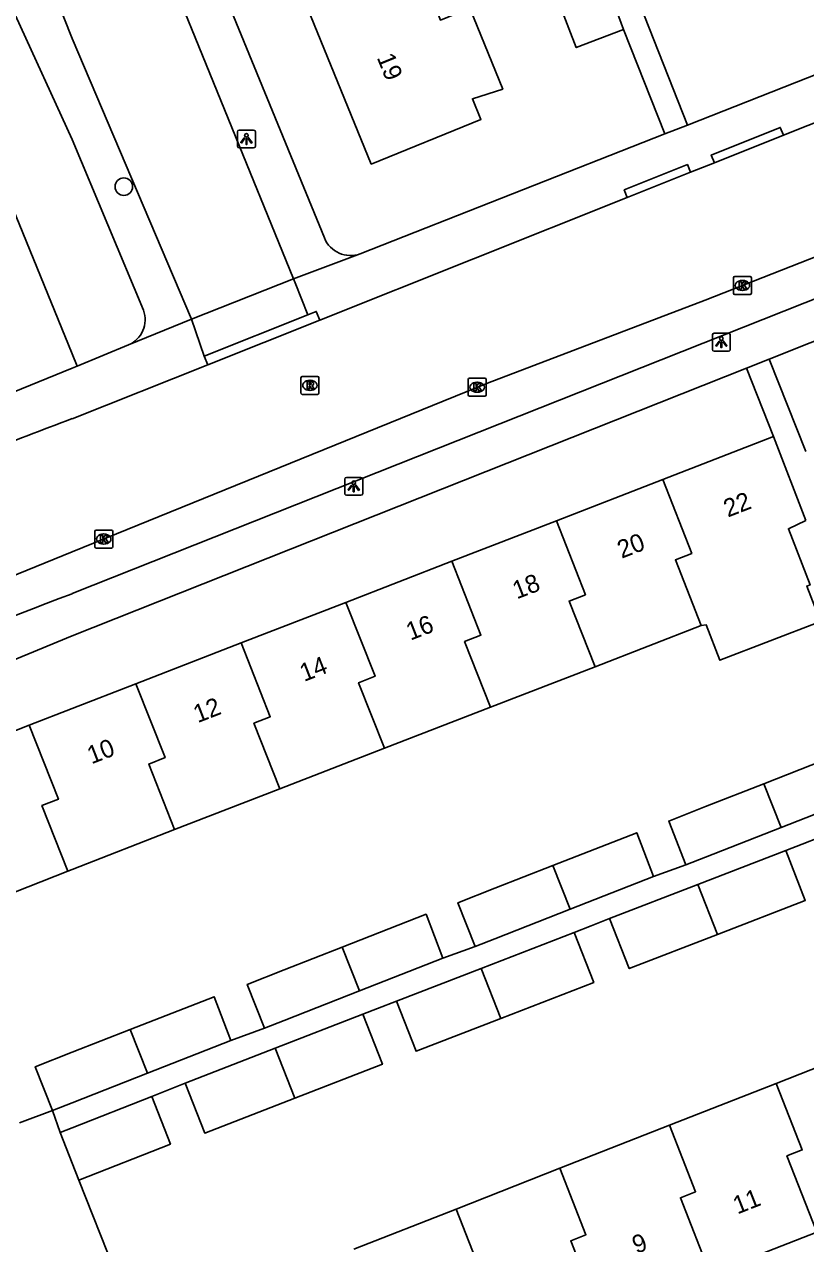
# Model space of a CAD drawing. Extents: x 162990 to 165007, y 383433 to 384336.
# Drawn here: x 163997.3 to 164040.8, y 383839.9 to 383907.8 of the extents above; entities that cross this region are included whole.
import ezdxf

# ---------------------------------------------------------------- set-up
doc = ezdxf.new("R2010")
doc.units = 0
for name, color, linetype in [('IMGEO_Boom', 7, 'Continuous'), ('IMGEO_Kolk', 7, 'Continuous'), ('IMGEO_Lichtpunt', 7, 'Continuous'), ('IMGEO_Pand', 7, 'Continuous'), ('IMGEO_Pand_nummerreeks', 7, 'Continuous'), ('IMGEO_Rijbaan_lokaal_open', 7, 'Continuous'), ('IMGEO_Rioolput', 7, 'Continuous'), ('IMGEO_Voetpad_open', 7, 'Continuous')]:
    doc.layers.add(name, color=color, linetype=linetype)

msp = doc.modelspace()

# ---------------------------------------------------------------- linework, layer by layer
at = {"layer": 'IMGEO_Boom'}
msp.add_circle((164002.875, 383898.73), 0.489, dxfattribs=at)
at = {"layer": 'IMGEO_Kolk'}
for p, q in [((164036.774, 383892.807), (164036.774, 383893.659)), ((164036.849, 383893.733), (164037.701, 383893.733)), ((164037.262, 383893.513), (164037.287, 383893.513)), ((164037.775, 383893.659), (164037.775, 383892.807)), ((164037.701, 383892.733), (164036.849, 383892.733)), ((164037.285, 383892.953), (164037.26, 383892.953)), ((164022.023, 383887.143), (164022.023, 383887.995)), ((164022.098, 383888.069), (164022.95, 383888.069)), ((164022.511, 383887.849), (164022.536, 383887.849)), ((164023.024, 383887.995), (164023.024, 383887.143)), ((164022.95, 383887.069), (164022.098, 383887.069)), ((164022.534, 383887.289), (164022.509, 383887.289)), ((164001.258, 383878.697), (164001.258, 383879.549)), ((164001.333, 383879.623), (164002.185, 383879.623)), ((164002.259, 383879.549), (164002.259, 383878.697)), ((164001.746, 383879.403), (164001.771, 383879.403)), ((164002.185, 383878.623), (164001.333, 383878.623)), ((164001.769, 383878.843), (164001.744, 383878.843))]:
    msp.add_line(p, q, dxfattribs=at)
for points in [[(164036.774, 383892.807), (164036.774, 383893.659)], [(164036.849, 383893.733), (164037.701, 383893.733)], [(164037.095, 383893.433), (164037.218, 383893.433), (164037.218, 383893.282), (164037.348, 383893.433), (164037.512, 383893.433), (164037.366, 383893.282), (164037.519, 383893.033), (164037.367, 383893.033), (164037.282, 383893.197), (164037.218, 383893.13), (164037.218, 383893.033), (164037.095, 383893.033), (164037.095, 383893.433)], [(164037.775, 383893.659), (164037.775, 383892.807)], [(164037.701, 383892.733), (164036.849, 383892.733)], [(164022.023, 383887.143), (164022.023, 383887.995)], [(164022.098, 383888.069), (164022.95, 383888.069)], [(164022.344, 383887.769), (164022.467, 383887.769), (164022.467, 383887.618), (164022.597, 383887.769), (164022.761, 383887.769), (164022.615, 383887.618), (164022.768, 383887.369), (164022.616, 383887.369), (164022.531, 383887.533), (164022.467, 383887.466), (164022.467, 383887.369), (164022.344, 383887.369), (164022.344, 383887.769)], [(164023.024, 383887.995), (164023.024, 383887.143)], [(164022.95, 383887.069), (164022.098, 383887.069)], [(164001.258, 383878.697), (164001.258, 383879.549)], [(164001.333, 383879.623), (164002.185, 383879.623)], [(164002.259, 383879.549), (164002.259, 383878.697)], [(164001.579, 383879.323), (164001.702, 383879.323), (164001.702, 383879.172), (164001.832, 383879.323), (164001.996, 383879.323), (164001.85, 383879.172), (164002.003, 383878.923), (164001.851, 383878.923), (164001.766, 383879.087), (164001.702, 383879.02), (164001.702, 383878.923), (164001.579, 383878.923), (164001.579, 383879.323)], [(164002.185, 383878.623), (164001.333, 383878.623)]]:
    msp.add_lwpolyline(points, dxfattribs=at)
for centre, start, end in [((164036.851, 383893.657), 91.55205, 178.44795), ((164036.851, 383893.657), 91.55205, 178.44795), ((164037.699, 383893.657), 1.55205, 88.44795), ((164037.699, 383893.657), 1.55205, 88.44795), ((164036.851, 383892.809), 181.55205, 268.44795), ((164036.851, 383892.809), 181.55205, 268.44795), ((164037.699, 383892.809), 271.55205, 358.44795), ((164037.699, 383892.809), 271.55205, 358.44795), ((164022.1, 383887.993), 91.55205, 178.44795), ((164022.1, 383887.993), 91.55205, 178.44795), ((164022.948, 383887.993), 1.55205, 88.44795), ((164022.948, 383887.993), 1.55205, 88.44795), ((164022.1, 383887.145), 181.55205, 268.44795), ((164022.1, 383887.145), 181.55205, 268.44795), ((164022.948, 383887.145), 271.55205, 358.44795), ((164022.948, 383887.145), 271.55205, 358.44795), ((164001.335, 383879.547), 91.55205, 178.44795), ((164001.335, 383879.547), 91.55205, 178.44795), ((164002.183, 383879.547), 1.55205, 88.44795), ((164002.183, 383879.547), 1.55205, 88.44795), ((164001.335, 383878.699), 181.55205, 268.44795), ((164001.335, 383878.699), 181.55205, 268.44795), ((164002.183, 383878.699), 271.55205, 358.44795), ((164002.183, 383878.699), 271.55205, 358.44795)]:
    msp.add_arc(centre, 0.0765, start, end, dxfattribs=at)
for centre, major_axis, ratio, start_param, end_param in [((164037.261, 383893.233), (-0.387, 0.002), 0.722429, 4.712389, 7.853982), ((164037.286, 383893.233), (-0.39, 0.002), 0.717154, 1.570796, 4.712389), ((164022.51, 383887.569), (-0.387, 0.002), 0.722429, 4.712389, 7.853982), ((164022.535, 383887.569), (-0.39, 0.002), 0.717154, 1.570796, 4.712389), ((164001.745, 383879.123), (-0.387, 0.002), 0.722429, 4.712389, 7.853982), ((164001.77, 383879.123), (-0.39, 0.002), 0.717154, 1.570796, 4.712389)]:
    msp.add_ellipse(centre, major_axis=major_axis, ratio=ratio, start_param=start_param, end_param=end_param, dxfattribs=at)
at = {"layer": 'IMGEO_Lichtpunt'}
for p, q in [((164009.193, 383901.785), (164009.193, 383900.978)), ((164009.193, 383901.785), (164009.193, 383900.978)), ((164010.095, 383901.88), (164009.287, 383901.88)), ((164010.095, 383901.88), (164009.287, 383901.88)), ((164010.189, 383900.978), (164010.189, 383901.785)), ((164010.189, 383900.978), (164010.189, 383901.785)), ((164009.287, 383900.884), (164010.095, 383900.884)), ((164009.287, 383900.884), (164010.095, 383900.884)), ((164035.608, 383890.478), (164035.608, 383889.671)), ((164035.608, 383890.478), (164035.608, 383889.671)), ((164036.51, 383890.573), (164035.702, 383890.573)), ((164036.51, 383890.573), (164035.702, 383890.573)), ((164036.604, 383889.671), (164036.604, 383890.478)), ((164036.604, 383889.671), (164036.604, 383890.478)), ((164035.702, 383889.577), (164036.51, 383889.577)), ((164035.702, 383889.577), (164036.51, 383889.577)), ((164015.162, 383882.459), (164015.162, 383881.652)), ((164015.162, 383882.459), (164015.162, 383881.652)), ((164016.064, 383882.554), (164015.256, 383882.554)), ((164016.064, 383882.554), (164015.256, 383882.554)), ((164016.158, 383881.652), (164016.158, 383882.459)), ((164016.158, 383881.652), (164016.158, 383882.459)), ((164015.256, 383881.558), (164016.064, 383881.558)), ((164015.256, 383881.558), (164016.064, 383881.558))]:
    msp.add_line(p, q, dxfattribs=at)
for points in [[(164009.567, 383901.449), (164009.606, 383901.421), (164009.418, 383901.159), (164009.38, 383901.186), (164009.567, 383901.449)], [(164009.669, 383901.401), (164009.716, 383901.401), (164009.716, 383901.079), (164009.669, 383901.079), (164009.669, 383901.401)], [(164009.779, 383901.421), (164009.817, 383901.448), (164010.004, 383901.186), (164009.965, 383901.158), (164009.779, 383901.421)], [(164035.982, 383890.142), (164036.021, 383890.114), (164035.833, 383889.852), (164035.795, 383889.879), (164035.982, 383890.142)], [(164036.084, 383890.094), (164036.131, 383890.094), (164036.131, 383889.772), (164036.084, 383889.772), (164036.084, 383890.094)], [(164036.194, 383890.114), (164036.232, 383890.141), (164036.419, 383889.879), (164036.38, 383889.851), (164036.194, 383890.114)], [(164015.536, 383882.123), (164015.575, 383882.095), (164015.387, 383881.833), (164015.349, 383881.86), (164015.536, 383882.123)], [(164015.638, 383882.075), (164015.685, 383882.075), (164015.685, 383881.753), (164015.638, 383881.753), (164015.638, 383882.075)], [(164015.748, 383882.095), (164015.786, 383882.122), (164015.973, 383881.86), (164015.934, 383881.832), (164015.748, 383882.095)]]:
    msp.add_lwpolyline(points, dxfattribs=at)
for centre in [(164009.692, 383901.583), (164036.107, 383890.276), (164015.661, 383882.257)]:
    msp.add_circle(centre, 0.0994, dxfattribs=at)
for centre, start, end in [((164009.287, 383901.785), 90, 180), ((164009.287, 383901.785), 90, 180), ((164010.095, 383901.785), 0, 90), ((164010.095, 383901.785), 0, 90), ((164009.287, 383900.978), 180, 270), ((164009.287, 383900.978), 180, 270), ((164010.095, 383900.978), 270, 0), ((164010.095, 383900.978), 270, 360), ((164035.702, 383890.478), 90, 180), ((164035.702, 383890.478), 90, 180), ((164036.51, 383890.478), 0, 90), ((164036.51, 383890.478), 0, 90), ((164035.702, 383889.671), 180, 270), ((164035.702, 383889.671), 180, 270), ((164036.51, 383889.671), 270, 0), ((164036.51, 383889.671), 270, 360), ((164015.256, 383882.459), 90, 180), ((164015.256, 383882.459), 90, 180), ((164016.064, 383882.459), 0, 90), ((164016.064, 383882.459), 0, 90), ((164015.256, 383881.652), 180, 270), ((164015.256, 383881.652), 180, 270), ((164016.064, 383881.652), 270, 0), ((164016.064, 383881.652), 270, 360)]:
    msp.add_arc(centre, 0.0946, start, end, dxfattribs=at)
at = {"layer": 'IMGEO_Pand'}
for points in [[(164028.022, 383914.647), (164030.669, 383907.485)], [(164025.298, 383913.569), (164028.032, 383906.469), (164030.669, 383907.485)], [(164013.083, 383908.672), (164016.634, 383899.987), (164022.732, 383902.472), (164022.262, 383903.627), (164023.948, 383904.165), (164022.121, 383908.669), (164020.483, 383908.004), (164019.203, 383911.158)], [(163996.678, 383897.58), (164000, 383889.428), (164000.279, 383888.743)], [(164000.279, 383888.743), (164000, 383888.629), (163994.349, 383886.325)], [(164032.842, 383882.428), (164039.01, 383884.819)], [(164039.01, 383884.819), (164040.81, 383880.155)], [(164026.929, 383880.136), (164032.842, 383882.428)], [(164034.992, 383874.308), (164033.552, 383877.958), (164034.462, 383878.318), (164032.842, 383882.428)], [(164021.115, 383877.882), (164026.929, 383880.136)], [(164026.929, 383880.136), (164028.549, 383876.026), (164027.639, 383875.666), (164029.079, 383872.016)], [(164040.81, 383880.155), (164039.832, 383879.698), (164041.038, 383876.572), (164040.851, 383876.5), (164041.611, 383874.532), (164036.023, 383872.374), (164035.263, 383874.343), (164034.992, 383874.308)], [(164015.224, 383875.598), (164021.115, 383877.882)], [(164021.115, 383877.882), (164022.735, 383873.772), (164021.825, 383873.412), (164023.265, 383869.762)], [(164009.4, 383873.339), (164015.224, 383875.598)], [(164017.374, 383867.478), (164015.934, 383871.128), (164016.844, 383871.488), (164015.224, 383875.598)], [(164034.992, 383874.308), (164029.079, 383872.016)], [(164003.547, 383871.07), (164009.4, 383873.339)], [(164011.55, 383865.219), (164010.11, 383868.869), (164011.02, 383869.229), (164009.4, 383873.339)], [(164029.079, 383872.016), (164023.265, 383869.762)], [(163997.613, 383868.756), (164000, 383869.697), (164003.547, 383871.07)], [(164003.547, 383871.07), (164005.167, 383866.96), (164004.257, 383866.6), (164005.697, 383862.95)], [(164023.265, 383869.762), (164017.374, 383867.478)], [(163991.679, 383866.418), (163997.613, 383868.756)], [(163999.762, 383860.636), (163998.323, 383864.285), (163999.233, 383864.645), (163997.613, 383868.756)], [(164017.374, 383867.478), (164011.55, 383865.219)], [(164038.467, 383865.501), (164043.125, 383867.327)], [(164043.125, 383867.327), (164044.064, 383864.882), (164039.427, 383863.066)], [(164034.136, 383860.993), (164033.177, 383863.427), (164035.23, 383864.232), (164038.467, 383865.501)], [(164038.467, 383865.501), (164039.427, 383863.066)], [(164011.55, 383865.219), (164005.697, 383862.95)], [(164005.697, 383862.95), (164000, 383860.73), (163999.762, 383860.636)], [(164026.74, 383860.955), (164031.398, 383862.781), (164032.337, 383860.336)], [(164039.427, 383863.066), (164035.23, 383861.422), (164034.136, 383860.993)], [(164039.683, 383861.792), (164034.803, 383859.901)], [(164035.895, 383857.119), (164040.775, 383859.011), (164039.683, 383861.792)], [(163999.762, 383860.636), (163993.829, 383858.298)], [(164022.409, 383856.447), (164021.45, 383858.881), (164023.503, 383859.686), (164026.74, 383860.955)], [(164027.7, 383858.52), (164026.74, 383860.955)], [(164032.337, 383860.336), (164027.7, 383858.52)], [(164034.803, 383859.901), (164029.893, 383857.998)], [(164035.895, 383857.119), (164034.803, 383859.901)], [(164027.7, 383858.52), (164023.503, 383856.876), (164022.409, 383856.447)], [(164015.025, 383856.412), (164019.683, 383858.238), (164020.622, 383855.793)], [(164029.893, 383857.998), (164030.985, 383855.216), (164035.895, 383857.119)], [(164027.916, 383857.231), (164022.756, 383855.231)], [(164023.847, 383852.45), (164029.008, 383854.45), (164027.916, 383857.231)], [(164010.694, 383851.904), (164009.735, 383854.338), (164011.788, 383855.143), (164015.025, 383856.412)], [(164015.985, 383853.977), (164015.025, 383856.412)], [(164020.622, 383855.793), (164015.985, 383853.977)], [(164022.756, 383855.231), (164018.032, 383853.401)], [(164023.847, 383852.45), (164022.756, 383855.231)], [(164015.985, 383853.977), (164011.788, 383852.333), (164010.694, 383851.904)], [(164003.235, 383851.828), (164007.895, 383853.655), (164008.834, 383851.21)], [(164018.032, 383853.401), (164019.124, 383850.619), (164023.847, 383852.45)], [(164011.29, 383850.787), (164016.167, 383852.678)], [(164012.382, 383848.006), (164017.26, 383849.896), (164016.167, 383852.678)], [(163998.906, 383847.321), (163997.947, 383849.755), (164000, 383850.56), (164003.235, 383851.828)], [(164004.196, 383849.393), (164003.235, 383851.828)], [(164008.834, 383851.21), (164004.196, 383849.393)], [(164039.151, 383848.825), (164044.939, 383851.097)], [(164006.284, 383848.847), (164011.29, 383850.787)], [(164011.29, 383850.787), (164012.382, 383848.006)], [(164004.196, 383849.393), (164000, 383847.75), (163998.906, 383847.321)], [(164012.382, 383848.006), (164007.376, 383846.066), (164006.284, 383848.847)], [(164033.22, 383846.498), (164039.151, 383848.825)], [(164041.417, 383840.56), (164039.756, 383844.796), (164040.601, 383845.131), (164039.151, 383848.825)], [(163999.326, 383846.101), (164000, 383846.365), (164004.427, 383848.103)], [(164000.366, 383843.452), (164005.467, 383845.455), (164004.427, 383848.103)], [(164027.123, 383844.105), (164033.22, 383846.498)], [(164035.485, 383838.232), (164033.825, 383842.468), (164034.67, 383842.803), (164033.22, 383846.498)], [(163999.326, 383846.101), (164000, 383844.384), (164000.366, 383843.452)], [(164021.352, 383841.84), (164027.123, 383844.105)], [(164027.123, 383844.105), (164028.573, 383840.411), (164027.728, 383840.076), (164029.389, 383835.84)], [(164015.675, 383839.613), (164021.352, 383841.84)], [(164021.352, 383841.84), (164022.802, 383838.146), (164021.957, 383837.811), (164023.617, 383833.575)], [(164041.417, 383840.56), (164035.485, 383838.232)]]:
    msp.add_lwpolyline(points, dxfattribs=at)
at = {"layer": 'IMGEO_Rijbaan_lokaal_open'}
for points in [[(164012.318, 383893.596), (164004.63, 383912.46), (164000, 383924.312), (163980.791, 383970.272)], [(163988.382, 383936.273), (164000, 383906.981), (164006.644, 383891.352)], [(164052.116, 383906.595), (164039.558, 383901.589)], [(164039.558, 383901.589), (164035.716, 383900.057)], [(164035.716, 383900.057), (164034.39, 383899.529)], [(163987.058, 383873.134), (164000, 383878.405), (164023.091, 383887.799), (164035.209, 383892.416), (164053.748, 383899.705)], [(164034.39, 383899.529), (164030.872, 383898.127)], [(164030.872, 383898.127), (164013.768, 383891.308)], [(164006.644, 383891.352), (164012.318, 383893.596)], [(164013.768, 383891.308), (164007.539, 383888.825)], [(164007.539, 383888.825), (164000, 383885.82)]]:
    msp.add_lwpolyline(points, dxfattribs=at)
msp.add_arc((164167.038, 383443.254), 473.04, 110.67806, 111.97431, dxfattribs=at)
at = {"layer": 'IMGEO_Rioolput'}
for p, q in [((164012.725, 383887.248), (164012.725, 383888.1)), ((164012.8, 383888.174), (164013.652, 383888.174)), ((164013.213, 383887.954), (164013.238, 383887.954)), ((164013.726, 383888.1), (164013.726, 383887.248)), ((164013.652, 383887.174), (164012.8, 383887.174)), ((164013.236, 383887.394), (164013.211, 383887.394))]:
    msp.add_line(p, q, dxfattribs=at)
for points in [[(164012.725, 383887.248), (164012.725, 383888.1)], [(164012.8, 383888.174), (164013.652, 383888.174)], [(164013.314, 383887.872), (164013.062, 383887.874), (164013.062, 383887.474)], [(164013.24, 383887.793), (164013.186, 383887.793), (164013.186, 383887.712)], [(164013.186, 383887.712), (164013.238, 383887.712)], [(164013.726, 383888.1), (164013.726, 383887.248)], [(164013.652, 383887.174), (164012.8, 383887.174)], [(164013.062, 383887.474), (164013.186, 383887.474), (164013.186, 383887.636), (164013.197, 383887.636)], [(164013.244, 383887.607), (164013.315, 383887.474), (164013.455, 383887.474), (164013.39, 383887.6)]]:
    msp.add_lwpolyline(points, dxfattribs=at)
for centre, radius, start, end in [((164012.802, 383888.098), 0.0765, 91.55205, 178.44795), ((164012.802, 383888.098), 0.0765, 91.55205, 178.44795), ((164013.222, 383887.901), 0.19, 274.7715, 282.96867), ((164013.246, 383887.697), 0.0964, 77.00612, 93.18647), ((164013.26, 383887.754), 0.0378, 276.66336, 79.67722), ((164013.313, 383887.762), 0.109, 350.36119, 89.41601), ((164013.311, 383887.762), 0.112, 277.58423, 350.98172), ((164013.65, 383888.098), 0.0765, 1.55205, 88.44795), ((164013.65, 383888.098), 0.0765, 1.55205, 88.44795), ((164012.802, 383887.25), 0.0765, 181.55205, 268.44795), ((164012.802, 383887.25), 0.0765, 181.55205, 268.44795), ((164013.196, 383887.583), 0.0533, 26.02933, 88.69889), ((164013.295, 383887.547), 0.108, 29.51342, 73.79051), ((164013.65, 383887.25), 0.0765, 271.55205, 358.44795), ((164013.65, 383887.25), 0.0765, 271.55205, 358.44795)]:
    msp.add_arc(centre, radius, start, end, dxfattribs=at)
for centre, major_axis, ratio, start_param, end_param in [((164013.212, 383887.674), (-0.387, 0.002), 0.722429, 4.712389, 7.853982), ((164013.237, 383887.674), (-0.39, 0.002), 0.717154, 1.570796, 4.712389)]:
    msp.add_ellipse(centre, major_axis=major_axis, ratio=ratio, start_param=start_param, end_param=end_param, dxfattribs=at)
at = {"layer": 'IMGEO_Voetpad_open'}
for points in [[(164014.027, 383895.881), (164000, 383930.097), (163992.717, 383948.402), (163983.442, 383971.144)], [(164016.569, 383946.93), (164034.216, 383902.156)], [(163985.056, 383936.458), (163990.031, 383924.252), (163996.829, 383908.289), (164000, 383901.361), (164003.968, 383891.854)], [(164034.216, 383902.156), (164051.609, 383909.011)], [(164030.669, 383907.485), (164032.962, 383901.662)], [(164032.962, 383901.662), (164034.216, 383902.156)], [(164035.716, 383900.057), (164035.543, 383900.49), (164039.383, 383902.029), (164039.558, 383901.589)], [(164032.962, 383901.662), (164016.024, 383894.987)], [(164030.872, 383898.127), (164030.704, 383898.551), (164034.22, 383899.959), (164034.39, 383899.529)], [(164000, 383876.082), (164050.894, 383896.295)], [(164012.318, 383893.596), (164016.024, 383894.987)], [(164054.487, 383889.592), (164052.546, 383894.614), (164038.761, 383889.135)], [(164013.112, 383891.606), (164012.406, 383893.374), (164012.318, 383893.596)], [(164013.768, 383891.308), (164013.577, 383891.791), (164013.112, 383891.606)], [(164003.132, 383889.92), (164006.644, 383891.352)], [(164006.644, 383891.352), (164007.348, 383889.306)], [(164007.348, 383889.306), (164013.112, 383891.606)], [(164003.132, 383889.92), (164000.279, 383888.743)], [(164007.539, 383888.825), (164007.348, 383889.306)], [(164038.761, 383889.135), (164037.495, 383888.632)], [(164038.761, 383889.135), (164040.807, 383883.987)], [(164037.495, 383888.632), (164000, 383873.731), (163986.263, 383868.057), (163974.417, 383862.714), (163972.918, 383862.038), (163973.946, 383859.431)], [(164039.01, 383884.819), (164037.495, 383888.632)], [(164039.683, 383861.792), (164040.602, 383862.148), (164041.548, 383862.515)], [(164034.136, 383860.993), (164032.337, 383860.336)], [(164027.916, 383857.231), (164028.864, 383857.599), (164029.893, 383857.998)], [(164022.409, 383856.447), (164020.622, 383855.793)], [(164016.167, 383852.678), (164016.975, 383852.991), (164018.032, 383853.401)], [(164010.694, 383851.904), (164008.834, 383851.21)], [(164004.427, 383848.103), (164006.284, 383848.847)], [(163997.076, 383846.64), (163998.906, 383847.321)], [(163998.906, 383847.321), (163999.326, 383846.101)], [(164000.366, 383843.452), (164002.349, 383838.439), (164000, 383837.541), (163999.153, 383837.217)]]:
    msp.add_lwpolyline(points, dxfattribs=at)
for centre, radius, start, end in [((164015.492, 383896.477), 1.582, 202.12932, 289.63727), ((164002.503, 383891.34), 1.553, 293.9063, 19.33945), ((164128.402, 383536.365), 363.173, 110.70499, 114.58528)]:
    msp.add_arc(centre, radius, start, end, dxfattribs=at)

# ---------------------------------------------------------------- texts
at = {"layer": 'IMGEO_Pand_nummerreeks'}
for s, rotation, p in [('19', 292.23628, (164016.93, 383905.92)), ('22', 21.20687, (164036.467, 383880.313)), ('20', 21.20687, (164030.558, 383878.021)), ('18', 21.20687, (164024.729, 383875.76)), ('16', 21.20687, (164018.812, 383873.463)), ('14', 21.20687, (164012.898, 383871.168)), ('12', 21.20687, (164006.981, 383868.873)), ('10', 21.20687, (164001.074, 383866.581)), ('11', 21.42654, (164036.995, 383841.532)), ('9', 21.42654, (164031.389, 383839.332))]:
    msp.add_text(s, height=1, rotation=rotation, dxfattribs=at).set_placement(p)

doc.saveas('drawing.dxf')
